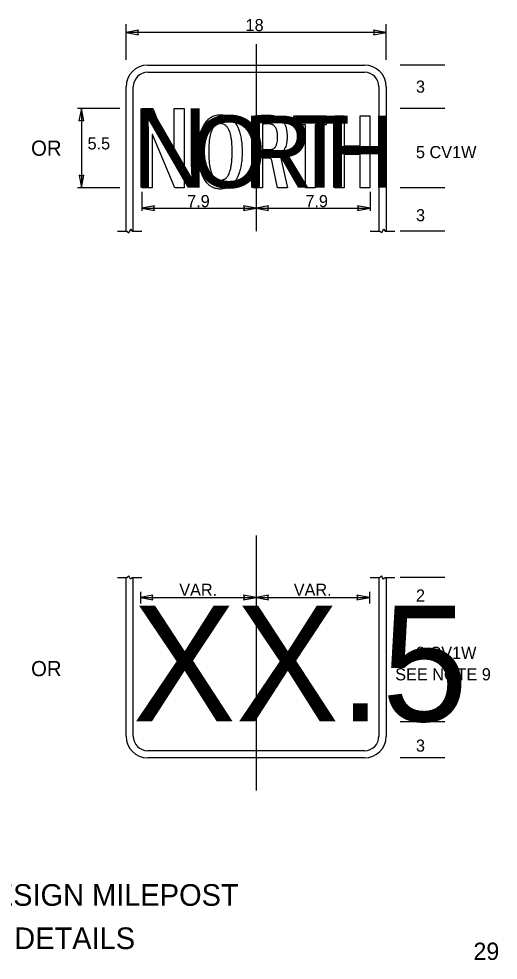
# Model space of a CAD drawing. Extents: x 56108 to 56734, y 11696 to 12110.
# Drawn here: x 56623.6 to 56734.2, y 11706.5 to 11923.8 of the extents above; entities that cross this region are included whole.
import ezdxf

# ---------------------------------------------------------------- set-up
doc = ezdxf.new("R2010")
doc.units = 0
for name, color, linetype in [('CL_dp', 7, 'Continuous'), ('GSDims', 7, 'Continuous'), ('SignPanel', 7, 'Continuous'), ('TextMisc', 7, 'Continuous'), ('TextShtNo', 7, 'Continuous')]:
    doc.layers.add(name, color=color, linetype=linetype)

msp = doc.modelspace()

# ---------------------------------------------------------------- linework, layer by layer
at = {"layer": 'CL_dp'}
for p, q in [((56678.32, 11917.97), (56678.32, 11874.82)), ((56678.32, 11804.56), (56678.32, 11745.62))]:
    msp.add_line(p, q, dxfattribs=at)
at = {"layer": 'GSDims'}
for p, q in [((56648.32, 11914.4), (56648.32, 11922.62)), ((56651.22, 11921.24), (56648.32, 11920.7)), ((56651, 11920.7), (56651.22, 11921.24)), ((56708.32, 11920.7), (56705.42, 11921.26)), ((56705.42, 11921.26), (56705.64, 11920.7)), ((56708.32, 11914.4), (56708.32, 11922.62)), ((56708.32, 11920.7), (56648.32, 11920.7)), ((56648.32, 11920.7), (56651.22, 11920.14)), ((56651.22, 11920.14), (56651, 11920.7)), ((56705.64, 11920.7), (56705.42, 11920.16)), ((56705.42, 11920.16), (56708.32, 11920.7)), ((56721.86, 11913.16), (56711.57, 11913.16)), ((56646.9, 11903.16), (56637.16, 11903.16)), ((56638.03, 11903.16), (56637.47, 11900.26)), ((56638.03, 11903.16), (56638.03, 11884.82)), ((56638.57, 11900.26), (56638.03, 11903.16)), ((56721.86, 11903.16), (56711.57, 11903.16)), ((56637.47, 11900.26), (56638.03, 11900.48)), ((56638.03, 11900.48), (56638.57, 11900.26)), ((56638.03, 11887.5), (56637.49, 11887.72)), ((56637.49, 11887.72), (56638.03, 11884.82)), ((56638.03, 11884.82), (56638.59, 11887.72)), ((56638.59, 11887.72), (56638.03, 11887.5)), ((56646.9, 11884.82), (56637.16, 11884.82)), ((56721.86, 11884.82), (56711.57, 11884.82)), ((56651.99, 11883.91), (56651.99, 11879.49)), ((56704.65, 11883.91), (56704.65, 11879.49)), ((56654.89, 11880.65), (56651.99, 11880.11)), ((56651.99, 11880.11), (56678.32, 11880.11)), ((56651.99, 11880.11), (56654.89, 11879.55)), ((56654.67, 11880.11), (56654.89, 11880.65)), ((56654.89, 11879.55), (56654.67, 11880.11)), ((56678.32, 11880.11), (56675.42, 11880.67)), ((56675.42, 11880.67), (56675.64, 11880.11)), ((56675.64, 11880.11), (56675.42, 11879.57)), ((56675.42, 11879.57), (56678.32, 11880.11)), ((56681.22, 11880.65), (56678.32, 11880.11)), ((56678.32, 11880.11), (56704.65, 11880.11)), ((56678.32, 11880.11), (56681.22, 11879.55)), ((56681, 11880.11), (56681.22, 11880.65)), ((56681.22, 11879.55), (56681, 11880.11)), ((56704.65, 11880.11), (56701.75, 11880.67)), ((56701.75, 11880.67), (56701.97, 11880.11)), ((56701.97, 11880.11), (56701.75, 11879.57)), ((56701.75, 11879.57), (56704.65, 11880.11)), ((56721.86, 11874.82), (56711.57, 11874.82)), ((56721.86, 11794.82), (56711.57, 11794.82)), ((56651.64, 11791.55), (56651.64, 11788.86)), ((56654.54, 11790.74), (56651.64, 11790.2)), ((56654.32, 11790.2), (56654.54, 11790.74)), ((56678.32, 11790.2), (56675.42, 11790.76)), ((56675.42, 11790.76), (56675.64, 11790.2)), ((56681.22, 11790.74), (56678.32, 11790.2)), ((56681, 11790.2), (56681.22, 11790.74)), ((56704.45, 11790.2), (56701.55, 11790.76)), ((56701.55, 11790.76), (56701.77, 11790.2)), ((56704.45, 11791.55), (56704.45, 11788.86)), ((56651.64, 11790.2), (56678.32, 11790.2)), ((56651.64, 11790.2), (56654.54, 11789.64)), ((56654.54, 11789.64), (56654.32, 11790.2)), ((56675.64, 11790.2), (56675.42, 11789.66)), ((56675.42, 11789.66), (56678.32, 11790.2)), ((56678.32, 11790.2), (56704.45, 11790.2)), ((56678.32, 11790.2), (56681.22, 11789.64)), ((56681.22, 11789.64), (56681, 11790.2)), ((56701.77, 11790.2), (56701.55, 11789.66)), ((56701.55, 11789.66), (56704.45, 11790.2)), ((56721.86, 11788.16), (56711.57, 11788.16)), ((56721.86, 11761.49), (56711.57, 11761.49)), ((56721.86, 11753.16), (56711.57, 11753.16))]:
    msp.add_line(p, q, dxfattribs=at)
at = {"layer": 'SignPanel'}
for p, q in [((56646.32, 11874.82), (56648.53, 11874.82)), ((56648.53, 11874.82), (56648.95, 11874.41)), ((56649.36, 11875.24), (56648.95, 11874.41)), ((56649.36, 11875.24), (56649.77, 11874.82)), ((56649.77, 11874.82), (56651.99, 11874.82)), ((56704.65, 11874.82), (56706.87, 11874.82)), ((56706.87, 11874.82), (56707.28, 11874.41)), ((56707.69, 11875.24), (56707.28, 11874.41)), ((56707.69, 11875.24), (56708.1, 11874.82)), ((56708.1, 11874.82), (56710.32, 11874.82)), ((56648.53, 11794.82), (56648.95, 11795.24)), ((56649.36, 11794.41), (56648.95, 11795.24)), ((56706.87, 11794.82), (56707.28, 11795.24)), ((56707.69, 11794.41), (56707.28, 11795.24)), ((56646.32, 11794.82), (56648.53, 11794.82)), ((56649.36, 11794.41), (56649.77, 11794.82)), ((56649.77, 11794.82), (56651.99, 11794.82)), ((56704.65, 11794.82), (56706.87, 11794.82)), ((56707.69, 11794.41), (56708.1, 11794.82)), ((56708.1, 11794.82), (56710.32, 11794.82))]:
    msp.add_line(p, q, dxfattribs=at)
for points in [[(56653.32, 11913.16), (56703.32, 11913.16)], [(56653.32, 11911.49), (56703.32, 11911.49)], [(56648.32, 11874.82), (56648.32, 11908.16)], [(56649.99, 11874.82), (56649.99, 11908.16)], [(56706.65, 11908.16), (56706.65, 11874.82)], [(56708.32, 11908.16), (56708.32, 11874.82)], [(56659.59, 11884.82), (56654.45, 11897.11), (56654.38, 11897.11), (56654.38, 11884.82), (56652.06, 11884.82), (56652.06, 11903.1), (56654.49, 11903.1), (56659.41, 11890.85), (56659.45, 11890.85), (56659.45, 11903.1), (56661.76, 11903.1), (56661.76, 11884.82), (56659.59, 11884.82)], [(56659.59, 11884.82), (56654.45, 11897.11), (56654.38, 11897.11), (56654.38, 11884.82), (56652.06, 11884.82), (56652.06, 11903.1), (56654.49, 11903.1), (56659.41, 11890.85), (56659.45, 11890.85), (56659.45, 11903.1), (56661.76, 11903.1), (56661.76, 11884.82), (56659.59, 11884.82)], [(56681.41, 11891.66), (56679.8, 11891.66), (56679.8, 11884.82), (56677.59, 11884.82), (56677.59, 11901.35)], [(56681.41, 11891.66), (56679.8, 11891.66), (56679.8, 11884.82), (56677.59, 11884.82), (56677.59, 11901.35)], [(56679.8, 11899.5), (56679.8, 11893.64), (56681.41, 11893.64)], [(56679.8, 11899.5), (56679.8, 11893.64), (56681.41, 11893.64)], [(56691.95, 11899.38), (56691.95, 11884.82), (56689.74, 11884.82), (56689.74, 11899.38), (56687.17, 11899.38), (56687.17, 11901.44), (56694.51, 11901.44), (56694.51, 11899.38), (56691.95, 11899.38)], [(56691.95, 11899.38), (56691.95, 11884.82), (56689.74, 11884.82), (56689.74, 11899.38), (56687.17, 11899.38), (56687.17, 11901.44), (56694.51, 11901.44), (56694.51, 11899.38), (56691.95, 11899.38)], [(56702.35, 11884.82), (56702.35, 11892.48), (56698.67, 11892.48), (56698.67, 11884.82), (56696.46, 11884.82), (56696.46, 11901.44), (56698.67, 11901.44), (56698.67, 11894.54), (56702.35, 11894.54), (56702.35, 11901.44), (56704.56, 11901.44), (56704.56, 11884.82), (56702.35, 11884.82)], [(56702.35, 11884.82), (56702.35, 11892.48), (56698.67, 11892.48), (56698.67, 11884.82), (56696.46, 11884.82), (56696.46, 11901.44), (56698.67, 11901.44), (56698.67, 11894.54), (56702.35, 11894.54), (56702.35, 11901.44), (56704.56, 11901.44), (56704.56, 11884.82), (56702.35, 11884.82)], [(56683.25, 11884.82), (56682.04, 11890.72)], [(56683.25, 11884.82), (56682.04, 11890.72)], [(56684.01, 11891.66), (56685.56, 11884.82), (56683.25, 11884.82)], [(56684.01, 11891.66), (56685.56, 11884.82), (56683.25, 11884.82)], [(56683.61, 11892.48), (56683.61, 11892.45)], [(56683.61, 11892.48), (56683.61, 11892.45)], [(56648.32, 11758.16), (56648.32, 11794.82)], [(56649.99, 11758.16), (56649.99, 11794.82)], [(56706.65, 11794.82), (56706.65, 11758.16)], [(56708.32, 11794.82), (56708.32, 11758.16)], [(56703.32, 11754.82), (56653.32, 11754.82)], [(56703.32, 11753.16), (56653.32, 11753.16)]]:
    msp.add_lwpolyline(points, dxfattribs=at)
for centre, radius, start, end in [((56653.32, 11908.16), 5, 90, 180), ((56703.32, 11908.16), 5, 0, 90), ((56653.32, 11908.16), 3.33, 90, 180), ((56703.32, 11908.16), 3.33, 0, 90), ((56653.32, 11758.16), 5, 180, 270), ((56653.32, 11758.16), 3.33, 180, 270), ((56703.32, 11758.16), 5, 270, 360), ((56703.32, 11758.16), 3.33, 270, 360)]:
    msp.add_arc(centre, radius, start, end, dxfattribs=at)
for points in [[(56665.11, 11893.14), (56665.12, 11893.74), (56665.14, 11894.88), (56665.33, 11896.27), (56665.59, 11897.53), (56665.88, 11898.44), (56666.22, 11899.17), (56666.48, 11899.63), (56666.77, 11900.05), (56667.16, 11900.5), (56667.52, 11900.83), (56667.83, 11901.06), (56668.15, 11901.26), (56668.59, 11901.47), (56669.16, 11901.63), (56669.67, 11901.7), (56669.98, 11901.7), (56670.09, 11901.7)], [(56665.11, 11893.14), (56665.12, 11893.74), (56665.14, 11894.88), (56665.33, 11896.27), (56665.59, 11897.53), (56665.88, 11898.44), (56666.22, 11899.17), (56666.48, 11899.63), (56666.77, 11900.05), (56667.16, 11900.5), (56667.52, 11900.83), (56667.83, 11901.06), (56668.15, 11901.26), (56668.59, 11901.47), (56669.16, 11901.63), (56669.67, 11901.7), (56669.98, 11901.7), (56670.09, 11901.7)], [(56670.09, 11901.7), (56670.19, 11901.7), (56670.51, 11901.7), (56671.01, 11901.63), (56671.59, 11901.47), (56672.02, 11901.26), (56672.34, 11901.06), (56672.65, 11900.83), (56673.01, 11900.5), (56673.4, 11900.05), (56673.69, 11899.63), (56673.95, 11899.17), (56674.29, 11898.44), (56674.59, 11897.53), (56674.87, 11896.27), (56675.06, 11894.88), (56675.09, 11893.74), (56675.1, 11893.14)], [(56670.09, 11901.7), (56670.19, 11901.7), (56670.51, 11901.7), (56671.01, 11901.63), (56671.59, 11901.47), (56672.02, 11901.26), (56672.34, 11901.06), (56672.65, 11900.83), (56673.01, 11900.5), (56673.4, 11900.05), (56673.69, 11899.63), (56673.95, 11899.17), (56674.29, 11898.44), (56674.59, 11897.53), (56674.87, 11896.27), (56675.06, 11894.88), (56675.09, 11893.74), (56675.1, 11893.14)], [(56677.59, 11901.35), (56677.75, 11901.37), (56678.06, 11901.42), (56678.52, 11901.47), (56678.95, 11901.52), (56679.38, 11901.55), (56679.8, 11901.57), (56680.23, 11901.59), (56680.67, 11901.6), (56680.97, 11901.6), (56681.12, 11901.6)], [(56677.59, 11901.35), (56677.75, 11901.37), (56678.06, 11901.42), (56678.52, 11901.47), (56678.95, 11901.52), (56679.38, 11901.55), (56679.8, 11901.57), (56680.23, 11901.59), (56680.67, 11901.6), (56680.97, 11901.6), (56681.12, 11901.6)], [(56681.12, 11901.6), (56681.29, 11901.6), (56681.71, 11901.59), (56682.27, 11901.51), (56682.79, 11901.37), (56683.2, 11901.22), (56683.58, 11901.02), (56683.92, 11900.78), (56684.18, 11900.55), (56684.37, 11900.35), (56684.55, 11900.13), (56684.8, 11899.78), (56685.1, 11899.16), (56685.36, 11898.3), (56685.46, 11897.44), (56685.47, 11896.89), (56685.48, 11896.7)], [(56681.12, 11901.6), (56681.29, 11901.6), (56681.71, 11901.59), (56682.27, 11901.51), (56682.79, 11901.37), (56683.2, 11901.22), (56683.58, 11901.02), (56683.92, 11900.78), (56684.18, 11900.55), (56684.37, 11900.35), (56684.55, 11900.13), (56684.8, 11899.78), (56685.1, 11899.16), (56685.36, 11898.3), (56685.46, 11897.44), (56685.47, 11896.89), (56685.48, 11896.7)], [(56670.09, 11899.64), (56670.02, 11899.64), (56669.85, 11899.64), (56669.59, 11899.59), (56669.35, 11899.51), (56669.14, 11899.41), (56668.98, 11899.3), (56668.83, 11899.17), (56668.66, 11899), (56668.46, 11898.76), (56668.21, 11898.36), (56668.01, 11897.9), (56667.78, 11897.21), (56667.63, 11896.52), (56667.5, 11895.56), (56667.42, 11894.49), (56667.41, 11893.62), (56667.4, 11893.16)], [(56670.09, 11899.64), (56670.02, 11899.64), (56669.85, 11899.64), (56669.59, 11899.59), (56669.35, 11899.51), (56669.14, 11899.41), (56668.98, 11899.3), (56668.83, 11899.17), (56668.66, 11899), (56668.46, 11898.76), (56668.21, 11898.36), (56668.01, 11897.9), (56667.78, 11897.21), (56667.63, 11896.52), (56667.5, 11895.56), (56667.42, 11894.49), (56667.41, 11893.62), (56667.4, 11893.16)], [(56672.81, 11893.16), (56672.8, 11893.63), (56672.79, 11894.51), (56672.7, 11895.59), (56672.57, 11896.55), (56672.42, 11897.24), (56672.22, 11897.86), (56672.07, 11898.2), (56671.91, 11898.5), (56671.74, 11898.77), (56671.54, 11899.01), (56671.37, 11899.18), (56671.19, 11899.32), (56670.95, 11899.47), (56670.62, 11899.59), (56670.33, 11899.64), (56670.15, 11899.64), (56670.09, 11899.64)], [(56672.81, 11893.16), (56672.8, 11893.63), (56672.79, 11894.51), (56672.7, 11895.59), (56672.57, 11896.55), (56672.42, 11897.24), (56672.22, 11897.86), (56672.07, 11898.2), (56671.91, 11898.5), (56671.74, 11898.77), (56671.54, 11899.01), (56671.37, 11899.18), (56671.19, 11899.32), (56670.95, 11899.47), (56670.62, 11899.59), (56670.33, 11899.64), (56670.15, 11899.64), (56670.09, 11899.64)], [(56681.17, 11899.6), (56681.05, 11899.6), (56680.83, 11899.6), (56680.48, 11899.59), (56680.14, 11899.56), (56679.91, 11899.52), (56679.8, 11899.5)], [(56681.17, 11899.6), (56681.05, 11899.6), (56680.83, 11899.6), (56680.48, 11899.59), (56680.14, 11899.56), (56679.91, 11899.52), (56679.8, 11899.5)], [(56683.27, 11896.57), (56683.26, 11896.75), (56683.26, 11897.11), (56683.21, 11897.57), (56683.13, 11898.01), (56683.03, 11898.34), (56682.9, 11898.6), (56682.8, 11898.78), (56682.68, 11898.94), (56682.52, 11899.12), (56682.37, 11899.25), (56682.24, 11899.34), (56682.09, 11899.42), (56681.89, 11899.51), (56681.62, 11899.57), (56681.38, 11899.6), (56681.22, 11899.6), (56681.17, 11899.6)], [(56683.27, 11896.57), (56683.26, 11896.75), (56683.26, 11897.11), (56683.21, 11897.57), (56683.13, 11898.01), (56683.03, 11898.34), (56682.9, 11898.6), (56682.8, 11898.78), (56682.68, 11898.94), (56682.52, 11899.12), (56682.37, 11899.25), (56682.24, 11899.34), (56682.09, 11899.42), (56681.89, 11899.51), (56681.62, 11899.57), (56681.38, 11899.6), (56681.22, 11899.6), (56681.17, 11899.6)], [(56681.41, 11893.64), (56681.45, 11893.64), (56681.56, 11893.65), (56681.75, 11893.66), (56681.96, 11893.71), (56682.15, 11893.77), (56682.33, 11893.85), (56682.49, 11893.96), (56682.63, 11894.09), (56682.74, 11894.22), (56682.82, 11894.32), (56682.89, 11894.45), (56683, 11894.65), (56683.12, 11895.02), (56683.25, 11895.67), (56683.26, 11896.22), (56683.27, 11896.57)], [(56681.41, 11893.64), (56681.45, 11893.64), (56681.56, 11893.65), (56681.75, 11893.66), (56681.96, 11893.71), (56682.15, 11893.77), (56682.33, 11893.85), (56682.49, 11893.96), (56682.63, 11894.09), (56682.74, 11894.22), (56682.82, 11894.32), (56682.89, 11894.45), (56683, 11894.65), (56683.12, 11895.02), (56683.25, 11895.67), (56683.26, 11896.22), (56683.27, 11896.57)], [(56685.48, 11896.7), (56685.47, 11896.42), (56685.46, 11895.79), (56685.34, 11894.95), (56685.14, 11894.31), (56684.98, 11893.95), (56684.81, 11893.64), (56684.57, 11893.28), (56684.22, 11892.91), (56683.9, 11892.65), (56683.68, 11892.52), (56683.61, 11892.48)], [(56685.48, 11896.7), (56685.47, 11896.42), (56685.46, 11895.79), (56685.34, 11894.95), (56685.14, 11894.31), (56684.98, 11893.95), (56684.81, 11893.64), (56684.57, 11893.28), (56684.22, 11892.91), (56683.9, 11892.65), (56683.68, 11892.52), (56683.61, 11892.48)], [(56670.09, 11884.53), (56669.98, 11884.53), (56669.67, 11884.54), (56669.17, 11884.61), (56668.6, 11884.77), (56668.17, 11884.97), (56667.84, 11885.18), (56667.54, 11885.41), (56667.17, 11885.73), (56666.78, 11886.19), (56666.5, 11886.61), (56666.23, 11887.08), (56665.89, 11887.81), (56665.59, 11888.72), (56665.32, 11889.99), (56665.14, 11891.39), (56665.12, 11892.55), (56665.11, 11893.14)], [(56670.09, 11884.53), (56669.98, 11884.53), (56669.67, 11884.54), (56669.17, 11884.61), (56668.6, 11884.77), (56668.17, 11884.97), (56667.84, 11885.18), (56667.54, 11885.41), (56667.17, 11885.73), (56666.78, 11886.19), (56666.5, 11886.61), (56666.23, 11887.08), (56665.89, 11887.81), (56665.59, 11888.72), (56665.32, 11889.99), (56665.14, 11891.39), (56665.12, 11892.55), (56665.11, 11893.14)], [(56667.4, 11893.16), (56667.41, 11892.69), (56667.42, 11891.79), (56667.5, 11890.7), (56667.63, 11889.73), (56667.78, 11889.03), (56667.99, 11888.41), (56668.13, 11888.06), (56668.29, 11887.75), (56668.47, 11887.48), (56668.67, 11887.23), (56668.84, 11887.07), (56669.02, 11886.92), (56669.27, 11886.77), (56669.6, 11886.65), (56669.89, 11886.6), (56670.08, 11886.59), (56670.14, 11886.59)], [(56667.4, 11893.16), (56667.41, 11892.69), (56667.42, 11891.79), (56667.5, 11890.7), (56667.63, 11889.73), (56667.78, 11889.03), (56667.99, 11888.41), (56668.13, 11888.06), (56668.29, 11887.75), (56668.47, 11887.48), (56668.67, 11887.23), (56668.84, 11887.07), (56669.02, 11886.92), (56669.27, 11886.77), (56669.6, 11886.65), (56669.89, 11886.6), (56670.08, 11886.59), (56670.14, 11886.59)], [(56675.1, 11893.14), (56675.09, 11892.55), (56675.06, 11891.39), (56674.87, 11889.99), (56674.59, 11888.73), (56674.29, 11887.81), (56673.95, 11887.08), (56673.69, 11886.61), (56673.4, 11886.19), (56673.02, 11885.73), (56672.65, 11885.41), (56672.34, 11885.18), (56672.02, 11884.97), (56671.59, 11884.77), (56671.01, 11884.61), (56670.51, 11884.54), (56670.19, 11884.53), (56670.09, 11884.53)], [(56675.1, 11893.14), (56675.09, 11892.55), (56675.06, 11891.39), (56674.87, 11889.99), (56674.59, 11888.73), (56674.29, 11887.81), (56673.95, 11887.08), (56673.69, 11886.61), (56673.4, 11886.19), (56673.02, 11885.73), (56672.65, 11885.41), (56672.34, 11885.18), (56672.02, 11884.97), (56671.59, 11884.77), (56671.01, 11884.61), (56670.51, 11884.54), (56670.19, 11884.53), (56670.09, 11884.53)], [(56670.14, 11886.59), (56670.2, 11886.59), (56670.38, 11886.6), (56670.58, 11886.63), (56670.77, 11886.69), (56670.9, 11886.74), (56671.08, 11886.83), (56671.24, 11886.94), (56671.4, 11887.07), (56671.57, 11887.25), (56671.76, 11887.49), (56672.01, 11887.9), (56672.21, 11888.37), (56672.43, 11889.07), (56672.57, 11889.77), (56672.7, 11890.73), (56672.79, 11891.81), (56672.8, 11892.7), (56672.81, 11893.16)], [(56670.14, 11886.59), (56670.2, 11886.59), (56670.38, 11886.6), (56670.58, 11886.63), (56670.77, 11886.69), (56670.9, 11886.74), (56671.08, 11886.83), (56671.24, 11886.94), (56671.4, 11887.07), (56671.57, 11887.25), (56671.76, 11887.49), (56672.01, 11887.9), (56672.21, 11888.37), (56672.43, 11889.07), (56672.57, 11889.77), (56672.7, 11890.73), (56672.79, 11891.81), (56672.8, 11892.7), (56672.81, 11893.16)], [(56682.04, 11890.72), (56682, 11890.85), (56681.96, 11891.05), (56681.88, 11891.28), (56681.84, 11891.39), (56681.8, 11891.46), (56681.77, 11891.5), (56681.73, 11891.55), (56681.69, 11891.59), (56681.63, 11891.62), (56681.58, 11891.64), (56681.51, 11891.66), (56681.46, 11891.66), (56681.42, 11891.66), (56681.41, 11891.66)], [(56682.04, 11890.72), (56682, 11890.85), (56681.96, 11891.05), (56681.88, 11891.28), (56681.84, 11891.39), (56681.8, 11891.46), (56681.77, 11891.5), (56681.73, 11891.55), (56681.69, 11891.59), (56681.63, 11891.62), (56681.58, 11891.64), (56681.51, 11891.66), (56681.46, 11891.66), (56681.42, 11891.66), (56681.41, 11891.66)], [(56683.61, 11892.45), (56683.62, 11892.44), (56683.64, 11892.43), (56683.67, 11892.42), (56683.7, 11892.39), (56683.74, 11892.35), (56683.79, 11892.3), (56683.83, 11892.23), (56683.88, 11892.1), (56683.94, 11891.92), (56683.99, 11891.75), (56684.01, 11891.66)], [(56683.61, 11892.45), (56683.62, 11892.44), (56683.64, 11892.43), (56683.67, 11892.42), (56683.7, 11892.39), (56683.74, 11892.35), (56683.79, 11892.3), (56683.83, 11892.23), (56683.88, 11892.1), (56683.94, 11891.92), (56683.99, 11891.75), (56684.01, 11891.66)]]:
    msp.add_open_spline(points, degree=3, dxfattribs=at)

# ---------------------------------------------------------------- texts
at = {"layer": 'GSDims'}
for s, height, p in [('18', 2.8, (56675.9, 11921)), ('3', 2.8, (56715.2, 11906.79)), ('OR', 3.5, (56626.43, 11892.23)), ('5.5', 2.8, (56639.45, 11893.68)), ('5 CV1W', 2.8, (56715.2, 11891.67)), ('7.9', 2.8, (56662.42, 11880.35)), ('7.9', 2.8, (56689.69, 11880.35)), ('3', 2.8, (56715.2, 11877.1)), ('VAR.', 2.8, (56660.6, 11790.6)), ('VAR.', 2.8, (56687.01, 11790.6)), ('2', 2.8, (56715.2, 11789.27)), ('8 CV1W', 2.8, (56715.2, 11776.04)), ('OR', 3.5, (56626.43, 11772.05)), ('SEE NOTE 9', 2.8, (56710.41, 11771.08)), ('3', 2.8, (56715.2, 11754.62))]:
    msp.add_text(s, height=height, dxfattribs=at).set_placement(p)
at = {"layer": 'SignPanel'}
for s, height, p in [('N', 18.33, (56649.59, 11884.82)), ('N', 18.33, (56649.59, 11884.82)), ('O', 16.67, (56663.38, 11884.82)), ('O', 16.67, (56663.38, 11884.82)), ('R', 16.67, (56675.34, 11884.82)), ('R', 16.67, (56675.34, 11884.82)), ('T', 16.67, (56686.31, 11884.82)), ('T', 16.67, (56686.31, 11884.82)), ('H', 16.67, (56694.21, 11884.82)), ('H', 16.67, (56694.21, 11884.82)), ('XX.5', 26.667, (56649.85, 11761.63))]:
    msp.add_text(s, height=height, dxfattribs=at).set_placement(p)
at = {"layer": 'TextMisc'}
for s, p in [('SPECIAL DESIGN MILEPOST ', (56582.9, 11719.02)), ('      SIGN DETAILS      ', (56593.19, 11709.02))]:
    msp.add_text(s, height=5, rotation=360, dxfattribs=at).set_placement(p)
at = {"layer": 'TextShtNo'}
msp.add_text('29', height=4, rotation=360, dxfattribs=at).set_placement((56728.46, 11706.52))

doc.saveas('drawing.dxf')
